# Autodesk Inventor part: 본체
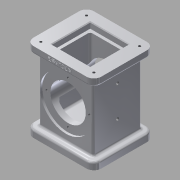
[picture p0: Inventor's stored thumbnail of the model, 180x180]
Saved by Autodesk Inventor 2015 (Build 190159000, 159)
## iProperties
Created: 2017-08
Part Number: 본체
Material: 알루미늄 6061
Document SubType Name: Modeling
Designer: Administrator
Density: 2.7 g/cm^3
Appearance: 알루미늄 - 평지
Mass: 869.091 g
Surface Area: 642.249 cm^2
Volume: 321.886 cm^3
Author: Administrator
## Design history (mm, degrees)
sketch "스케치1"
  geometry: L1 (-46, 41)-(46, 41); L2 (46, 41)-(46, -41); L3 (46, -41)-(-46, -41); L4 (-46, -41)-(-46, 41); L5 (46, -41)-(-46, 41); 2 further points
  constraints: 10 end point, 2 parallel, 1 coincident, 1 horizontal, 1 midpoint, 1 perpendicular
  dimensions: "d0" = 92 distance of L1.start L1.end; "d1" = 82 distance of L3.end L1.start
extrude "돌출1" new body sketch "스케치1" distance "d2" = 10; taper "d3" = 0 deg
sketch "스케치2"
  geometry: L1 (-37, 33)-(37, 33); L2 (37, 33)-(37, -33); L3 (37, -33)-(-37, -33); L4 (-37, -33)-(-37, 33); L5 (37, -33)-(-37, 33); 2 further points
  constraints: 10 end point, 2 parallel, 1 coincident, 1 horizontal, 1 midpoint, 1 perpendicular
  dimensions: "d4" = 74 distance of L1.start L1.end; "d5" = 66 distance of L1.end L2.end
extrude "돌출2" join sketch "스케치2" distance "d6" = 88; taper "d7" = 0 deg
sketch "스케치3"
  geometry: L1 (37, 33)-(37, -33) reference; L2 (37, -33)-(-37, -33) reference; L3 (-37, -33)-(-37, 33) reference; L4 (-37, 33)-(37, 33) reference; L5 (46, 41)-(-46, 41) reference; L6 (-46, 41)-(-46, -41) reference; L7 (-46, -41)-(46, -41) reference; L8 (46, -41)-(46, 41) reference; 1 further point
extrude "돌출3" join sketch "스케치3" distance "d8" = 10; taper "d9" = 0 deg
sketch "스케치4"
  geometry: L1 (24, -24)-(-24, -24); L2 (-24, -24)-(-24, 24); L3 (-24, 24)-(24, 24); L4 (24, 24)-(24, -24); L5 (-24, 24)-(24, -24); 2 further points
  constraints: 10 end point, 2 parallel, 2 perpendicular, 1 coincident, 1 horizontal, 1 midpoint
  dimensions: "d10" = 48 distance of L1.start L1.end
extrude "돌출4" cut sketch "스케치4" distance "d11" = 16; taper "d12" = 0 deg
sketch "스케치6"
  geometry: L1 (37, -10)-(37, 44); 1 further point
  constraints: 2 end point, 1 coincident, 1 vertical
  dimensions: "d48" = 54 distance of L1.start L1.end
hole "구멍1" sketch "스케치6" at (37, 44) diameter "d15" = 48; stored, may be unused: countersink angle "d19" = 90 deg, drill point angle "d21" = 118 deg; dims "d16" = 6, "d17" = 4, "d18" = 2, "d20" = 8
hole "구멍2" diameter "d24" = 70; stored, may be unused: countersink angle "d28" = 90 deg, drill point angle "d30" = 0 deg; dims "d25" = 6, "d26" = 4, "d27" = 2, "d29" = 3, "d35" = 10, "d36" = 10
sketch "스케치5"
  geometry: L1 (-22, 22)-(22, 22); L2 (22, 22)-(22, -22); L3 (22, -22)-(-22, -22); L4 (-22, -22)-(-22, 22); L5 (-26, 26)-(26, 26); L6 (26, 26)-(26, -26); L7 (26, -26)-(-26, -26); L8 (-26, -26)-(-26, 26); L9 (26, -26)-(-26, 26); L10 (22, -22)-(-22, 22); 2 further points
  constraints: 20 end point, 4 parallel, 3 perpendicular, 2 horizontal, 2 midpoint, 1 coincident, 1 collinear
  dimensions: "d13" = 52 distance of L5.start L5.end; "d14" = 44 distance of L1.start L1.end
extrude "돌출5" cut sketch "스케치5" distance "d33" = 82; taper "d34" = 0 deg
extrude "돌출6" cut sketch "스케치5" distance "d37" = 8; taper "d38" = 0 deg
sketch "스케치7"
  geometry: L1 (-36, 31)-(36, 31); L2 (36, 31)-(36, -31); L3 (36, -31)-(-36, -31); L4 (-36, -31)-(-36, 31); L5 (36, -31)-(-36, 31); 6 further points
  constraints: 10 end point, 5 coincident, 2 parallel, 1 horizontal, 1 midpoint, 1 perpendicular
  dimensions: "d39" = 72 distance of L1.start L1.end; "d40" = 62 distance of L1.end L2.end
hole "구멍3" sketch "스케치7" at (-36, 31), (36, 31), (-36, -31), (36, -31) diameter "d41" = 3.242; stored, may be unused: countersink angle "d45" = 90 deg, drill point angle "d47" = 118 deg; dims "d42" = 4, "d43" = 4, "d44" = 2, "d46" = 6
node "작업 평면1"
sketch "스케치8"
  geometry: C1 r 35 at (0, 0) reference; A1 r 29 centre (0, 0) between (0, 29) and (-29, 0); 3 further points
  constraints: 4 point on circle, 2 horizontal alignment, 2 vertical alignment, 1 centre point, 1 coincident
  dimensions: "d49" = 58 diameter of A1
hole "구멍4" sketch "스케치8" at (0, 29), (-29, 0), (0, -29), (29, 0) diameter "d50" = 3.242; stored, may be unused: countersink angle "d54" = 90 deg, drill point angle "d56" = 118 deg; dims "d51" = 4, "d52" = 4, "d53" = 2, "d55" = 6
sketch "스케치9"
  geometry: L1 (10, 33)-(-70, 33); 2 further points
  constraints: 2 end point, 1 coincident, 1 horizontal, 1 point on line
  dimensions: "d57" = 38 distance of point (-28, 33) L1.start; "d58" = 42 distance of point (-70, 33) point (-28, 33)
hole "구멍5" sketch "스케치9" at (-28, 33), (-70, 33) diameter "d65" = 4.134; stored, may be unused: countersink angle "d69" = 90 deg, drill point angle "d71" = 118 deg; dims "d66" = 10, "d67" = 4, "d68" = 2, "d70" = 20
fillet "모깎기1" dims "d59" = 10
fillet "모깎기2" dims "d60" = 3
fillet "모깎기3" dims "d61" = 3
chamfer "모따기1" distance "d62" = 1; stored, may be unused: second distance "d63" = 2, angle "d64" = 45 deg
node "작업 평면2"
sketch "스케치10"
  geometry: L1 (12.716, -0.432)-(59.284, -0.432); L2 (59.284, -0.432)-(59.284, -7.568); L3 (59.284, -7.568)-(12.716, -7.568); L4 (12.716, -7.568)-(12.716, -0.432); L5 (12.716, -0.432)-(59.284, -7.568); L6 (0, 0)-(72, 0) reference; 3 further points
  constraints: 2 end point, 2 midpoint, 1 vertical alignment, 2 other
  dimensions: "d73" = 4 distance from line of point (36, -4) L6
feature "엠보싱1" sketch "스케치10" dims "d0" = 92, "d1" = 82, "d74" = 0.5, "d75" = 0
node "솔리드1"
mirror "대칭1"
mirror "대칭2"
mirror "대칭3"
node "투영된 루프1"
other parameters: "d72" = 18.75
